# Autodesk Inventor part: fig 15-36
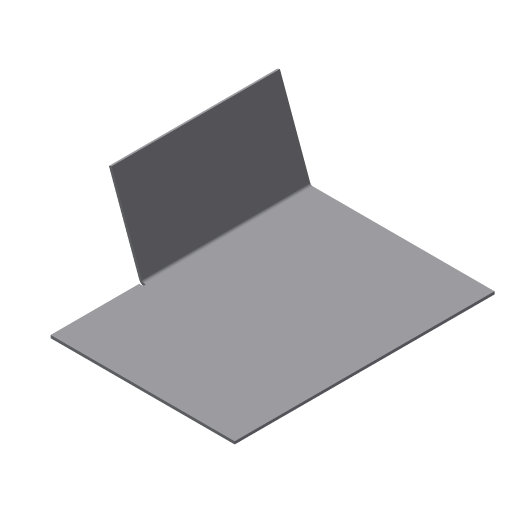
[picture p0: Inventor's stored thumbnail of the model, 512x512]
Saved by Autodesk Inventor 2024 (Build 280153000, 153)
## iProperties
Created: 2005-03
Part Number: fig 15-36
Document SubType Name: Sheet Metal
Designer: CADCIM
Manufacturer: Standard
Standards Organization: Custom
Density: 1 g/cm^3
Sheet Metal Rule: Default
Material: Generic
Appearance: Default
Author: CADCIM
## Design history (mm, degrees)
node "Face1"
  sketch "Sketch1"
    geometry: L1 (31.393, 35.714)-(-17.775, 35.714); L2 (-17.775, 35.714)-(-17.775, 5.625); L3 (-17.775, 5.625)-(-1.5, 5.625); L4 (-1.5, 5.625)-(-1.5, -10.705); L5 (-1.5, -10.705)-(31.393, -10.705); L6 (31.393, -10.705)-(31.393, 35.714)
    constraints: 12 end point, 4 parallel, 1 horizontal, 1 perpendicular
feature "Fold1" dims "d1" = 0.5 (= BendReliefWidth), "d2" = 0.25 (= BendReliefDepth), "d3" = 1 (= MinimumRemnant), "d4" = 0.5 (= BendRadius), "d5" = 70 deg, "d6" = 0.5 (= BendRadius), "d7" = 0.5 (= Thickness), "SeamGap" = 0.01
body "Solid1"
face "Plate1" dims "d7" = 0.5 (= Thickness)
sketch "Sketch3"
  geometry: L1 (16.275, -30.089)-(16.275, 0); L2 (16.275, -46.42)-(16.275, -30.089) reference; L3 (16.275, -30.089)-(0, -30.089) reference; L4 (0, 0)-(49.168, 0) reference
  constraints: 3 point on line, 2 end point, 1 vertical
other parameters: "Thickness" = 0.5, "BendRadius" = 0.5 (= Thickness), "BendReliefWidth" = 0.5 (= Thickness), "BendReliefDepth" = 0.25 (= 0.5 x Thickness), "CornerReliefSize" = 2 (= 4 x Thickness), "MinimumRemnant" = 1 (= 2 x Thickness), "TransitionRadius" = 0.5 (= BendRadius), "d0" = 0.5 (= BendRadius), "JacobiRadiusSize" = 0.5 (= Thickness), "GapSize" = 0.5 (= Thickness)
